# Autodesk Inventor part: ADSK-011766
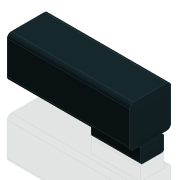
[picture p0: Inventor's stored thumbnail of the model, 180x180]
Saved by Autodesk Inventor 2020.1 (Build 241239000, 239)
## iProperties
Created: 1999-12
Part Number: ADSK-011766
Material: Aluminum
Document SubType Name: Modeling
Designer: tgregory
Density: 2.71 g/cm^3
Appearance: Servo Black
Mass: 4741.64 g
Surface Area: 988.221 cm^2
Volume: 1749.68 cm^3
Control State: 0
Checked Out: False
Master: False
Shininess: 0.0
Length Units: 11269
Angle Units: 11279
Time Units: 11290
Mass Units: 11283
Length Display Precision: 3
Angle Display Precision: 2
Compacted: True
Dimensions: 247x111x82 mm
Mass: 4,742 kg
Density: 0.0
Volumn: 0.0
Area: 0.0
PropertySet Name: Model Information
Author: tgregory
Revision Number: -
Title: ADSK-011766
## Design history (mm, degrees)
node "Extrusion1" dims "d2" = 81.99882 (= d0), "d3" = 0
node "Hole1" dims "d12" = 6.5, "d13" = 9.525, "d14" = 6.35, "d15" = 60 deg, "d16" = 8.001, "d17" = 118 deg, "d22" = 6
node "Extrusion2" dims "d9" = 28.99918, "d10" = 0
node "Fillet1" dims "d18" = 8.001
node "Fillet2" dims "d19" = 3.175
workplane "Work Plane1"
workplane "Work Plane2"
workaxis "Work Axis1"
node "Solide1"
node "Corps solides"
node "Corps surfaciques"
sketch "Sketch1"
  geometry: L1 (0, 0)-(242.999, 0); L2 (242.999, 0)-(242.999, 81.999); L3 (242.999, 81.999)-(0, 81.999); L4 (0, 81.999)-(0, 0); 1 further point
  constraints: 8 end point, 2 parallel, 1 coincident, 1 horizontal, 1 perpendicular
  dimensions: "d0" = 81.99882 distance between parallel lines of L3 L1; "d1" = 242.99926 distance between parallel lines of L2 L4
sketch "Sketch2"
  geometry: L1 (242.999, 0)-(242.999, -81.999) reference; L2 (0, 0)-(0, -81.999) reference; L3 (242.999, -40.999)-(148.999, -40.999); L4 (148.999, -40.999)-(148.999, -18); L5 (148.999, -40.999)-(148.999, -63.999); L6 (247, -41.588)-(247, -63.999); L7 (148.999, -63.999)-(247, -63.999); L8 (247, -18)-(247, -63.999); L9 (247, -18)-(148.999, -18); L10 (148.999, -18)-(148.999, -63.999)
  constraints: 16 end point, 6 perpendicular, 1 collinear, 1 midpoint
  dimensions: "d4" = 94.00032 distance from line of L1 L3.end; "d5" = 22.9997 distance from line of L3 L4.end; "d6" = 22.9997 distance from line of L5.end L3 (= d5); "d8" = 4.0005 distance between parallel lines of L6 L1
sketch "Sketch4"
  geometry: L1 (-40.999, 40.999)-(-81.999, 0) reference; L2 (-40.999, 40.999)-(-81.999, 81.999); L3 (-40.999, 40.999)-(0, 81.999); L4 (-40.999, 40.999)-(0, 0); A1 r 47.5 centre (-40.999, 40.999) between (-74.587, 74.587) and (-7.412, 74.587); 2 further points
  constraints: 8 end point, 4 point on circle, 4 point on line, 3 perpendicular, 1 centre point, 1 other
  dimensions: "d11" = 95 diameter of A1
other parameters: "d20" = -41.656, "d21" = -41.656
